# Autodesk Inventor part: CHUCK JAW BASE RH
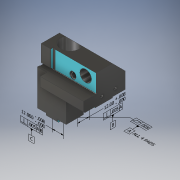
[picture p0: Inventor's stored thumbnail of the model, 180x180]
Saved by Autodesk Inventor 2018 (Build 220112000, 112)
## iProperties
Created: 2016-06
Part Number: CHUCK JAW BASE RH
Material: Steel
Document SubType Name: Modeling
Designer: thompsje
Density: 7.85 g/cm^3
Appearance: Plate
Engineer: faixa
Mass: 624.82 g
Surface Area: 186.501 cm^2
Volume: 79.595 cm^3
Author: thompsje
Title: CHUCK JAW BASE RH
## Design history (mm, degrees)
node "Annotations"
  node "Linear Dimension 1" dims "d21" = 0.5, "d131" = 55 (derived)
  node "Linear Dimension 2" dims "d21" = 0.5, "d132" = 23.26 (derived)
  node "Linear Dimension 3" dims "d21" = 0.5, "d133" = 10 (derived)
  node "Linear Dimension 4" dims "d21" = 0.5, "d136" = 11 (derived)
  node "Diameter Dimension 1" dims "d21" = 0.5, "d138" = 12 (derived)
  node "Linear Dimension 5" dims "d21" = 0.5, "d139" = 48 (derived)
  node "Linear Dimension 6" dims "d21" = 0.5, "d142" = 56 (derived)
  node "Linear Dimension 7" dims "d21" = 0.5, "d145" = 3.5 (derived)
  node "Leader Text 1"
  node "Linear Dimension 8" dims "d21" = 0.5, "d149" = 21 (derived)
  node "Linear Dimension 9" dims "d21" = 0.5, "d152" = 30 (derived)
  node "Linear Dimension 10" dims "d21" = 0.5, "d155" = 34 (derived)
  node "Radial Dimension 1" dims "d21" = 0.5, "d157" = 6 (derived)
  node "Linear Dimension 12" dims "d21" = 0.5, "d211" = 18 (derived)
  node "Linear Dimension 13" dims "d21" = 0.5, "d214" = 30 (derived)
  node "Linear Dimension 14" dims "d21" = 0.5, "d215" = 8 (derived)
  node "Linear Dimension 15" dims "d21" = 0.5, "d216" = 6 (derived)
  node "Linear Dimension 16" dims "d21" = 0.5, "d219" = 12 (derived)
  node "Linear Dimension 17" dims "d21" = 0.5, "d222" = 14 (derived)
  node "Linear Dimension 18" dims "d21" = 0.5, "d225" = 25.1 (derived)
  node "Linear Dimension 19" dims "d21" = 0.5, "d228" = 56 (derived)
  node "Linear Dimension 20" dims "d21" = 0.5, "d231" = 37 (derived)
  node "Linear Dimension 22" dims "d21" = 0.5, "d235" = 26 (derived)
  node "Linear Dimension 23" dims "d21" = 0.5, "d238" = 5 (derived)
  node "Thread Note 1" dims "d21" = 0.5, "d240" = 3.242 (derived)
  node "Angular Dimension 1" dims "d21" = 0.5, "d269" = 45 deg (derived)
  node "Linear Dimension 27" dims "d21" = 0.5, "d271" = 32 (derived)
  node "Linear Dimension 28" dims "d21" = 0.5, "d272" = 5 (derived)
  node "Linear Dimension 29" dims "d21" = 0.5, "d275" = 55.1 (derived)
  node "Linear Dimension 30" dims "d21" = 0.5, "d278" = 59.5 (derived)
  node "Radial Dimension 2" dims "d21" = 0.5, "d280" = 2 (derived)
  node "Linear Dimension 31" dims "d21" = 0.5, "d283" = 1.5 (derived)
  node "Linear Dimension 32" dims "d21" = 0.5, "d284" = 1.5 (derived)
  node "Linear Dimension 33" dims "d21" = 0.5, "d285" = 6 (derived)
  node "Linear Dimension 34" dims "d21" = 0.5, "d287" = 1 (derived)
  node "Angular Dimension 2" dims "d21" = 0.5, "d290" = 30 deg (derived)
  node "Linear Dimension 35" dims "d21" = 0.5, "d293" = 20 (derived)
  node "Linear Dimension 36" dims "d21" = 0.5, "d300" = 6.5 (derived)
  node "Linear Dimension 37" dims "d21" = 0.5, "d302" = 5 (derived)
  node "Linear Dimension 38" dims "d21" = 0.5, "d304" = 2 (derived)
  node "Linear Dimension 39" dims "d21" = 0.5, "d307" = 13 (derived)
  node "Linear Dimension 40" dims "d21" = 0.5, "d310" = 16 (derived)
  node "Thread Note 2" dims "d21" = 0.5, "d314" = 4.917 (derived)
  node "Linear Dimension 41" dims "d21" = 0.5, "d318" = 19.5 (derived)
  node "Linear Dimension 42" dims "d21" = 0.5, "d321" = 13 (derived)
  node "Linear Dimension 43" dims "d21" = 0.5, "d323" = 35 (derived)
  node "Linear Dimension 44" dims "d21" = 0.5, "d326" = 0.5 (derived)
  node "Linear Dimension 45" dims "d21" = 0.5, "d329" = 0.5 (derived)
  node "Linear Dimension 46" dims "d21" = 0.5, "d331" = 2.5 (derived)
  node "Angular Dimension 3" dims "d21" = 0.5, "d334" = 45 deg (derived)
  node "Angular Dimension 4" dims "d21" = 0.5, "d337" = 60 deg (derived)
  node "Linear Dimension 47" dims "d21" = 0.5, "d339" = 2 (derived)
  node "Linear Dimension 48" dims "d21" = 0.5, "d344" = 0.5 (derived)
  node "Radial Dimension 3" dims "d21" = 0.5, "d346" = 0.5 (derived)
  node "Radial Dimension 4" dims "d21" = 0.5, "d348" = 0.5 (derived)
  node "Linear Dimension 49" dims "d21" = 0.5, "d350" = 2 (derived)
  node "Linear Dimension 50" dims "d21" = 0.5, "d352" = 0.3 (derived)
  node "Linear Dimension 51" dims "d21" = 0.5, "d354" = 0.3 (derived)
  node "Linear Dimension 52" dims "d21" = 0.5, "d360" = 0.5 (derived)
  node "Radial Dimension 5" dims "d21" = 0.5, "d362" = 0.5 (derived)
  node "Leader Text 2"
  node "Linear Dimension 53" dims "d21" = 0.5, "d366" = 15.5 (derived)
  node "Linear Dimension 54" dims "d21" = 0.5, "d368" = 0.3 (derived)
  node "Linear Dimension 55" dims "d21" = 0.5, "d370" = 0.3 (derived)
  node "Radial Dimension 6" dims "d21" = 0.5, "d372" = 0.5 (derived)
  node "Surface Texture 1"
  node "Surface Texture 2"
  node "Surface Texture 3"
  node "Surface Texture 4"
  node "Surface Texture 5"
  node "Surface Texture 6"
  node "Surface Texture 7"
  node "Surface Texture 8"
  node "Surface Texture 9"
  node "General Note 1"
node "Tolerance Features"
  node "Planar Surface 1" dims "d129" = 6.98023 (derived), "d130" = 6.96265 (derived), "d131" = 55 (derived), "d132" = 23.26 (derived), "d133" = 10 (derived), "d134" = 6.47961 (derived), "d135" = 2.20671 (derived), "d136" = 11 (derived), "d137" = 28.46996 (derived), "d138" = 12 (derived), "d139" = 48 (derived), "d140" = 3.09077 (derived), "d141" = 9.45813 (derived), "d142" = 56 (derived), "d143" = 5.57016 (derived), "d144" = 4.10514 (derived), "d145" = 3.5 (derived), "d146" = -13.83051 (derived), "d147" = 2.64854 (derived), "d148" = 1.61489 (derived), "d149" = 21 (derived), "d150" = 1.70689 (derived), "d151" = 4.0494 (derived), "d152" = 30 (derived)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
  node "Datum Reference Frame 1"
  node "Slot 1" dims "d129" = 6.98023 (derived), "d130" = 6.96265 (derived), "d131" = 55 (derived), "d132" = 23.26 (derived), "d133" = 10 (derived), "d134" = 6.47961 (derived), "d135" = 2.20671 (derived), "d136" = 11 (derived), "d137" = 28.46996 (derived), "d138" = 12 (derived), "d139" = 48 (derived), "d140" = 3.09077 (derived), "d141" = 9.45813 (derived), "d142" = 56 (derived), "d143" = 5.57016 (derived), "d144" = 4.10514 (derived), "d145" = 3.5 (derived), "d146" = -13.83051 (derived), "d147" = 2.64854 (derived), "d148" = 1.61489 (derived), "d149" = 21 (derived), "d150" = 1.70689 (derived), "d151" = 4.0494 (derived), "d152" = 30 (derived)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
  node "Datum Reference Frame 2"
  node "Slab 1" dims "d129" = 6.98023 (derived), "d130" = 6.96265 (derived), "d131" = 55 (derived), "d132" = 23.26 (derived), "d133" = 10 (derived), "d134" = 6.47961 (derived), "d135" = 2.20671 (derived), "d136" = 11 (derived), "d137" = 28.46996 (derived), "d138" = 12 (derived), "d139" = 48 (derived), "d140" = 3.09077 (derived), "d141" = 9.45813 (derived), "d142" = 56 (derived), "d143" = 5.57016 (derived), "d144" = 4.10514 (derived), "d145" = 3.5 (derived), "d146" = -13.83051 (derived), "d147" = 2.64854 (derived), "d148" = 1.61489 (derived), "d149" = 21 (derived), "d150" = 1.70689 (derived), "d151" = 4.0494 (derived), "d152" = 30 (derived)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
  node "Datum Reference Frame 3"
sketch "Sketch1"
  geometry: L1 (-22.5, 29.5)-(-9.5, 29.5); L2 (-6, 29.5)-(-6, 26); L3 (-6, 21)-(-5.3, 21); L4 (6, 21)-(6, 21.7); L5 (6, 29.5)-(24, 29.5); L6 (24, 29.5)-(24, -5); L7 (24, -5)-(-1, -30); L8 (-1, -30)-(-20, -30); L9 (-20, -30)-(-20, -12.732); L10 (-20, -12.732)-(-17.75, -11.433); L11 (-18, -10.5)-(-21.5, -10.5); L12 (-22, -11)-(-31.1, -11); L13 (-31.1, -11)-(-31.1, -1.5); L14 (-29.6, 0)-(-24, 0); L15 (-24, 0)-(-24, 28); L16 (-24, 26)-(24, 26); L17 (-17.5, -13.5)-(-17.5, -8.5); L18 (-31.1, -1.5)-(-29.6, 0); L19 (-9.5, 29.5)-(-9.5, 26); L20 (-9.5, 26)-(-6, 26); L21 (-9.5, 29.5)-(-6, 29.5); L22 (-6, 26)-(-6, 21.7); L23 (-5.3, 21)-(5.3, 21); L24 (-6, 21.7)-(-6, 21); L25 (5.3, 21)-(6, 21); L26 (6, 21.7)-(6, 29.5); L27 (-22.5, 29.5)-(-24, 28); A1 r 0.5 centre (-21.5, -11) between (-21.5, -10.5) and (-22, -11); A2 r 0.5 centre (-18, -11) between (-17.75, -11.433) and (-18, -10.5); A3 r 0.5 centre (-5.7, 21.3) between (-6, 21.7) and (-5.3, 21); A4 r 0.5 centre (5.7, 21.3) between (5.3, 21) and (6, 21.7); A5 r 0.5 centre (-5.7, 21.3) between (-5.3, 21) and (-6, 21.7); A6 r 0.5 centre (5.7, 21.3) between (6, 21.7) and (5.3, 21); 4 further points
  constraints: 54 end point, 27 perpendicular, 12 point on circle, 11 point on line, 6 centre point, 5 parallel, 4 tangent, 2 horizontal, 2 horizontal alignment, 2 vertical, 2 vertical alignment, 1 midpoint
  dimensions: "d2" = 60 deg angle of L9 L10; "d3" = 18 distance of point (-24, 29.5) L2.start; "d4" = 59.5 distance between parallel lines of L5 L8; "d5" = 45 deg angle of L7 L8; "d6" = 55.1 distance between parallel lines of L6 L13; "d7" = 30 distance between parallel lines of L6 L2; "d8" = 12 distance between parallel lines of L4 L2; "d9" = 14 distance between parallel lines of L9 L2; "d10" = 25.1 distance between parallel lines of L13 L2 (derived); "d11" = 3.5 distance between parallel lines of L16 L1; "d12" = 56 distance between parallel lines of L8 L16 (derived); "d13" = 26 distance between parallel lines of L14 L16; "d14" = 37 distance between parallel lines of L12 L16; "d16" = 2 distance from line of L12.start L9; "d19" = 5 distance of L17.start L17.end; "d20" = 2.5 distance between parallel lines of L17 L9; "d21" = 0.5 radius of A1; "d22" = 0.5 radius of A2; "d23" = 2 distance from line of L17.end L11; "d24" = 5 distance between parallel lines of L3 L16; "d25" = 5 distance from line of L7.end L2; "d40" = 1.5 distance of L13.end point (-31.1, 0); "d41" = 1.5 distance of L14.start point (-31.1, 0) (= d40); "d42" = 15.5 distance between parallel lines of L19 L4; "d47" = 0.5 radius of A3; "d49" = 0.5 radius of A4; "d50" = 1.5 distance of L1.start point (-24, 29.5); "d51" = 1.5 distance of L15.end point (-24, 29.5) (= d50); "d122" = 0.2 distance edge to line of A3 L23; "d123" = 0.2 distance edge to line of A3 L22 (= d122); "d124" = 0.2 distance edge to line of A4 L26 (= d122); "d125" = 0.2 distance edge to line of A4 L23 (= d122)
extrude "Extrusion1" new body sketch "Sketch1" stored distance "d26" = 55; taper "d27" = 0 deg
sketch "Sketch2"
  geometry: L1 (32.5, 0)-(8.5, 0); L2 (2.5, 6)-(2.5, 26); L3 (-27.5, 29.5)-(27.5, 29.5) reference; L4 (2.5, 26)-(-5.8, 26); L5 (-6.5, 26)-(-6.5, 26.7); L6 (-7, 29.5)-(-18, 29.5); L7 (-18.5, 29)-(-18.5, 26.7); L8 (-18.5, 26)-(-19.2, 26); L9 (-32.5, 26)-(-32.5, 40); L10 (-32.5, 40)-(32.5, 40); L11 (32.5, 40)-(32.5, 0); L12 (-27.5, 26)-(27.5, 26); L13 (-18.5, 26.7)-(-18.5, 26); L14 (-19.2, 26)-(-32.5, 26); L15 (-6.5, 26.7)-(-6.5, 29); L16 (-5.8, 26)-(-6.5, 26); L17 (-18, 29.5)-(-18.5, 29); L18 (-7, 29.5)-(-6.5, 29); A1 r 6 centre (8.5, 6) between (2.5, 6) and (8.5, 0); A2 r 0.5 centre (-18.8, 26.3) between (-19.2, 26) and (-18.5, 26.7); A3 r 0.5 centre (-6.2, 26.3) between (-6.5, 26.7) and (-5.8, 26); A4 r 0.5 centre (-18.8, 26.3) between (-18.5, 26.7) and (-19.2, 26); A5 r 0.5 centre (-6.2, 26.3) between (-5.8, 26) and (-6.5, 26.7); 3 further points
  constraints: 34 end point, 16 perpendicular, 10 point on circle, 6 point on line, 5 centre point, 3 collinear, 2 tangent, 1 horizontal, 1 parallel, 1 vertical alignment
  dimensions: "d28" = 3.5 distance between parallel lines of L12 L3; "d29" = 34 distance from line of L5 L3.end; "d30" = 12 distance of point (-6.5, 29.5) point (-18.5, 29.5); "d31" = 26 distance between parallel lines of L1 L12; "d32" = 30 distance from line of L2 L3.start; "d33" = 6 radius of A1; "d34" = 5 distance from line of L9 L3.start; "d35" = 5 distance from line of L11 L3.end; "d36" = 40 distance of L10.end L1.start; "d56" = 1 diameter of A2; "d57" = 1 diameter of A3; "d58" = 0.5 distance of L6.end point (-18.5, 29.5); "d59" = 0.5 distance of L7.start point (-18.5, 29.5) (= d58); "d60" = 0.5 distance of L6.start point (-6.5, 29.5) (= d58); "d61" = 0.5 distance of L15.end point (-6.5, 29.5) (= d60); "d118" = 0.2 distance edge to line of A3 L4; "d119" = 0.2 distance edge to line of A3 L15 (= d118); "d120" = 0.2 distance edge to line of A2 L7 (= d118); "d121" = 0.2 distance edge to line of A2 L12 (= d118)
extrude "Extrusion2" cut sketch "Sketch2" extent not by distance; stored distance "d38" = 55; taper "d39" = 0 deg
sketch "Sketch3"
  geometry: L1 (21, 12.5)-(21, -2) reference; L2 (21, -1)-(21, -2) reference; L3 (21, 12.5)-(21, -1) reference; L4 (10, -2)-(10, -14.1); L5 (10, -2)-(-5, -2); L6 (-5, -2)-(-5, -14.1); L7 (-5, -14.1)-(10, -14.1); L8 (0, -2)-(8.3, -2) reference; L9 (0, -9.1)-(0, 0) reference; L10 (0, -9.1)-(55, -9.1) reference; 1 further point
  constraints: 8 end point, 2 vertical, 1 collinear, 1 horizontal, 1 perpendicular
  dimensions: "d62" = 11 distance between parallel lines of L1 L4; "d63" = 5 distance between parallel lines of L6 L9; "d64" = 5 distance between parallel lines of L7 L10
extrude "Extrusion3" cut sketch "Sketch3" extent not by distance; stored distance "d65" = 55; taper "d66" = 0 deg
sketch "Sketch4"
  geometry: L1 (10, -23)-(10, -30.1) reference; L2 (0, -19)-(55, -19) reference; L3 (10, -19)-(10, -16.5); L4 (10, -16.5)-(12, -16.5); L5 (12, -16.5)-(12.5, -17); L6 (12.5, -17)-(60, -17); L7 (0, -17)-(55, -17) reference; L8 (60, -17)-(60, -19); L9 (60, -19)-(10, -19); 1 further point
  constraints: 12 end point, 4 collinear, 2 perpendicular, 1 point on line, 1 vertical
  dimensions: "d67" = 2.5 distance from line of L5.end L1; "d68" = 45 deg angle of L5 L6; "d69" = 0.5 distance between parallel lines of L4 L6; "d71" = 5 distance from line of L8 L7.end
extrude "Extrusion4" cut sketch "Sketch4" stored distance "d72" = 55; taper "d73" = 0 deg
sketch "Sketch7"
  geometry: L1 (0, 25)-(55, 25) reference; L2 (55, 25)-(55, 0) reference; L3 (55, 13.453)-(35, 25); 1 further point
  constraints: 2 end point, 2 point on line
  dimensions: "d93" = 20 horizontal distance of L3.start L3.end; "d94" = 30 deg angle of L3 L1
extrude "Extrusion5" cut sketch "Sketch7" extent not by distance; stored distance "d95" = 10; taper "d96" = 0 deg
fillet "Fillet1" dims "d106" = 2
sketch "Sketch5"
  geometry: L1 (26, -24)-(26, 24) reference; L2 (21.7, -6)-(26, -6) reference; 3 further points
  constraints: 1 vertical alignment
  dimensions: "d74" = 32 distance from line of point (-6, -12) L1; "d75" = 6 distance from line of point (-6, -12) L2; "d76" = 8 distance from line of point (-6, 2) L2
hole "Hole1" sketch "Sketch5" at (-6, -12), (-6, 2) diameter "d77" = 3.242; stored, may be unused: countersink angle "d81" = 90 deg, drill point angle "d83" = 118 deg; dims "d78" = 10, "d79" = 4, "d80" = 2, "d82" = 13
sketch "Sketch6"
  geometry: L1 (33.3, 56)-(25, 56) reference; L2 (34, 58)-(34, 56.7) reference; 2 further points
  dimensions: "d84" = 48 distance from line of point (10.74, 8) L1; "d85" = 23.26 distance from line of point (10.74, 8) L2
hole "Hole2" sketch "Sketch6" at (10.74, 8) diameter "d86" = 12; stored, may be unused: countersink angle "d90" = 90 deg, drill point angle "d92" = 118 deg; dims "d87" = 6, "d88" = 4, "d89" = 2, "d91" = 8
sketch "Sketch8"
  geometry: L1 (20.5, 3.5)-(12.2, 3.5) reference; L2 (11.5, 33.5)-(11.5, 15.5) reference; 2 further points
  dimensions: "d97" = 1 distance from line of L1 point (5.5, 4.5); "d98" = 6 distance from line of point (5.5, 4.5) L2
workaxis "Work Axis1"
workplane "Work Plane1"
sketch "Sketch9"
  geometry: L1 (-13.472, 0)-(80.831, 0) reference; L2 (59.5, 4)-(59.5, -13) reference; L3 (59.5, -9.75)-(24.5, -9.75); L4 (24.5, -9.75)-(24.5, -7); L5 (23.5, 29)-(23.5, -19) reference; L6 (24.5, -7)-(24, -6.5); L7 (24, -6.5)-(0, -6.5); L8 (0, -6.5)-(0, 0); L9 (0, -4.5)-(0, -17.5) reference; L10 (0, 0)-(59.5, 0); 1 further point
  constraints: 12 end point, 5 point on line, 2 parallel, 1 horizontal, 1 vertical
  dimensions: "d100" = 19.5 diameter of L3 L1; "d101" = 13 diameter of L7 L1; "d102" = 35 distance of L3.start L3.end; "d103" = 0.5 horizontal distance of L4.end L6.end; "d104" = 45 deg angle of L4 L6
revolve "Revolution1 (Hole4)" sketch "Sketch9" stored, may be unused: angle "d105" = 90 deg
workplane "Work Plane2"
sketch "Sketch10"
  geometry: L1 (-42.7, 6)-(-36.991, 19.784); L2 (-56.7, 6)-(-38.277, 6) reference; L3 (-37.7, 0)-(-37.7, -7.1) reference; 1 further point
  constraints: 2 end point, 1 point on line
  dimensions: "d108" = 5 distance from line of L3 L1.start; "d167" = 67.5 deg angle of L2 L1
workaxis "Work Axis2"
workplane "Work Plane3"
sketch "Sketch11"
  geometry: 2 further points
hole "Hole3" sketch "Sketch11" at (0, 0) diameter "d109" = 4.917; stored, may be unused: countersink angle "d113" = 90 deg, drill point angle "d115" = 118 deg; dims "d110" = 15, "d111" = 6.5, "d112" = 2, "d114" = 18
sketch "Sketch12"
  geometry: C1 r 3.25 at (0, 0) reference; 1 further point
extrude "Extrusion6" cut sketch "Sketch12" distance "d116" = 10; taper "d117" = 0 deg
workaxis "Work Axis3"
  workpoint "Work Point1"
  workpoint "Work Point2"
sketch "Sketch13" dims "d24" = 5
  geometry: L1 (-1.3, 0)-(-2.3, 1) reference; L2 (-2.3, 1)-(-2.8, 1.5) reference; 1 further point
workplane "Work Plane4"
workplane "Work Plane5"
workplane "Work Plane6"
sketch "Sketch14" dims "d24" = 5
  geometry: L1 (-4.594, -19.221)-(-6.554, -18.409) reference; L2 (-6.554, -18.409)-(-10.189, -9.633) reference; L3 (-10.189, -9.633)-(-1.782, -6.15) reference; L4 (-1.129, -6.421)-(2.105, -5.081) reference; L5 (1.979, -4.124)-(1.692, -4.086) reference; L6 (1.692, -4.086)-(1.346, -3.25) reference; L7 (1.346, -3.25)-(2, -3.25) reference; L8 (2, -3.25)-(2, -2.458) reference; L9 (2, -2.458)-(18, -2.458) reference; L10 (18, -2.458)-(19.477, 0) reference; L11 (19.477, 0)-(18, 2.458) reference; L12 (18, 2.458)-(2, 2.458) reference; L13 (2, 2.458)-(2, 3.25) reference; L14 (2, 3.25)-(-1.346, 3.25) reference; L15 (-1.346, 3.25)-(-5.358, 12.934) reference; L16 (-5.358, 12.934)-(10.348, 19.44) reference; L17 (10.348, 19.44)-(43.012, 5.91) reference; L18 (43.012, 5.91)-(45.953, -1.188) reference; L19 (45.953, -1.188)-(1.607, -19.557) reference; L20 (1.607, -19.557)-(1.345, -18.926) reference; L21 (-1.268, -17.844)-(-4.594, -19.221) reference; L22 (2, 2.459)-(18, 2.458) reference; L23 (15, 2.459)-(15, -2.458); L24 (2, -2.458)-(18, -2.458) reference; L25 (18, -2.458)-(18, 2.458) reference; L26 (18, 2.458)-(18, -2.458); A1 r 0.5 centre (-1.32, -5.959) between (-1.782, -6.15) and (-1.129, -6.421) reference; A2 r 0.5 centre (1.913, -4.619) between (2.105, -5.081) and (1.979, -4.124) reference; A3 r 2 centre (-0.503, -19.691) between (1.345, -18.926) and (-1.268, -17.844) reference; 2 further points
  constraints: 4 end point, 2 point on line, 1 perpendicular, 1 vertical
  dimensions: "d297" = 13 distance between parallel lines of L13 L23 (derived)
  node "Project Cut Edges1" dims "d24" = 5
workplane "Work Plane7"
sketch "Sketch15" dims "d24" = 5
  geometry: L1 (59.5, 9.75)-(24.5, 9.75) reference; L2 (59.5, -9.75)-(24.5, -9.75) reference; L3 (24, -6.5)-(8.5, -6.5) reference; L4 (24, 6.5)-(8.5, 6.5) reference; L5 (24.5, 9.75)-(24.5, -9.75) reference; L6 (24.5, -7)-(24, -6.5) reference; L7 (24, 6.5)-(24, -6.5) reference
body "Solid1"
node "Projected Loop1"
node "Feature Control Frame 1"
node "Datum Identifier 1" dims "d21" = 0.5, "d129" = 6.98023 (derived), "d130" = 6.96265 (derived), "d131" = 55 (derived), "d132" = 23.26 (derived), "d133" = 10 (derived), "d134" = 6.47961 (derived), "d135" = 2.20671 (derived), "d136" = 11 (derived), "d137" = 28.46996 (derived), "d138" = 12 (derived), "d139" = 48 (derived), "d140" = 3.09077 (derived), "d141" = 9.45813 (derived), "d142" = 56 (derived), "d143" = 5.57016 (derived), "d144" = 4.10514 (derived), "d145" = 3.5 (derived), "d146" = -13.83051 (derived), "d147" = 2.64854 (derived), "d148" = 1.61489 (derived), "d149" = 21 (derived), "d150" = 1.70689 (derived), "d151" = 4.0494 (derived)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
node "Leader Text 3" dims "d2" = 60 deg, "d3" = 18, "d4" = 59.5, "d5" = 45 deg, "d6" = 55.1, "d7" = 30, "d8" = 12, "d9" = 14, "d10" = 25.1 (derived), "d11" = 3.5, "d12" = 56 (derived), "d13" = 26, "d14" = 37, "d16" = 2, "d19" = 5, "d20" = 2.5, "d21" = 0.5, "d22" = 0.5, "d23" = 2, "d24" = 5, "d25" = 5, "d40" = 1.5, "d41" = 1.5 (= d40), "d42" = 15.5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
node "Planar Surface 2"
node "Planar Surface 3"
node "Linear Dimension 56" dims "d21" = 0.5, "d398" = 12 (derived)
node "Feature Control Frame 2"
node "Datum Identifier 2" dims "d21" = 0.5, "d129" = 6.98023 (derived), "d130" = 6.96265 (derived), "d131" = 55 (derived), "d132" = 23.26 (derived), "d133" = 10 (derived), "d134" = 6.47961 (derived), "d135" = 2.20671 (derived), "d136" = 11 (derived), "d137" = 28.46996 (derived), "d138" = 12 (derived), "d139" = 48 (derived), "d140" = 3.09077 (derived), "d141" = 9.45813 (derived), "d142" = 56 (derived), "d143" = 5.57016 (derived), "d144" = 4.10514 (derived), "d145" = 3.5 (derived), "d146" = -13.83051 (derived), "d147" = 2.64854 (derived), "d148" = 1.61489 (derived), "d149" = 21 (derived), "d150" = 1.70689 (derived), "d151" = 4.0494 (derived)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
node "Planar Surface 4"
node "Planar Surface 5"
node "Linear Dimension 57" dims "d21" = 0.5, "d404" = 12 (derived)
node "Feature Control Frame 3"
node "Datum Identifier 3" dims "d21" = 0.5, "d129" = 6.98023 (derived), "d130" = 6.96265 (derived), "d131" = 55 (derived), "d132" = 23.26 (derived), "d133" = 10 (derived), "d134" = 6.47961 (derived), "d135" = 2.20671 (derived), "d136" = 11 (derived), "d137" = 28.46996 (derived), "d138" = 12 (derived), "d139" = 48 (derived), "d140" = 3.09077 (derived), "d141" = 9.45813 (derived), "d142" = 56 (derived), "d143" = 5.57016 (derived), "d144" = 4.10514 (derived), "d145" = 3.5 (derived), "d146" = -13.83051 (derived), "d147" = 2.64854 (derived), "d148" = 1.61489 (derived), "d149" = 21 (derived), "d150" = 1.70689 (derived), "d151" = 4.0494 (derived)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
other parameters: "d99" = 0, "d294" = 90 deg, "d295" = 90 deg, "d296" = 0, "d315" = 0
